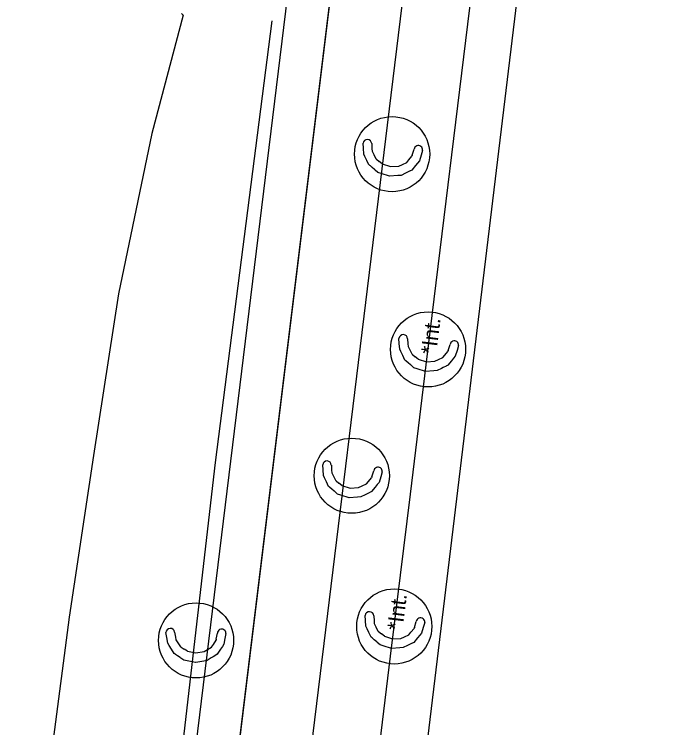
# Model space of a CAD drawing. Extents: x 400935 to 481562, y 415700 to 505362.
# Drawn here: x 481192.5 to 481394.6, y 490514.5 to 490732.9 of the extents above; entities that cross this region are included whole.
import ezdxf

# ---------------------------------------------------------------- set-up
doc = ezdxf.new("R2010")
doc.units = 0
for name, color, linetype in [('Coir Fiber Wattle with PAM Final CELL', 7, 'Continuous'), ('Earth Berm for Slope Drains Final', 7, 'Continuous'), ('Matting on Slope Note Final CELL', 7, 'Continuous'), ('Old_Level_2', 7, 'Continuous'), ('Scratch_Level_3', 7, 'Continuous'), ('Scratch_Level_4', 7, 'Continuous')]:
    doc.layers.add(name, color=color, linetype=linetype)

msp = doc.modelspace()

# ---------------------------------------------------------------- linework, layer by layer
at = {"layer": 'Coir Fiber Wattle with PAM Final CELL'}
for p, q in [((481301.89, 490693.33), (481301.98, 490691.77)), ((481301.98, 490691.77), (481302.03, 490690.98)), ((481302.03, 490690.98), (481302.52, 490690)), ((481314.32, 490689.81), (481314.88, 490691.59)), ((481302.52, 490690), (481303.17, 490688.7)), ((481303.35, 490688.55), (481303.17, 490688.7)), ((481303.35, 490688.55), (481304.21, 490687.85)), ((481313.27, 490688.36), (481314.21, 490689.5)), ((481314.32, 490689.81), (481314.21, 490689.5)), ((481305.14, 490687.11), (481304.21, 490687.85)), ((481305.14, 490687.11), (481307.66, 490686.34)), ((481307.67, 490686.33), (481307.66, 490686.34)), ((481307.67, 490686.33), (481310.21, 490686.45)), ((481310.21, 490686.45), (481311.3, 490686.96)), ((481311.3, 490686.96), (481312.61, 490687.57)), ((481312.61, 490687.57), (481313.27, 490688.36)), ((481289.55, 490594.9), (481289.63, 490593.35)), ((481289.63, 490593.35), (481289.68, 490592.56)), ((481289.68, 490592.56), (481290.17, 490591.57)), ((481301.97, 490591.39), (481302.54, 490593.16)), ((481290.17, 490591.57), (481290.82, 490590.28)), ((481291, 490590.13), (481290.82, 490590.28)), ((481291, 490590.13), (481291.87, 490589.43)), ((481300.92, 490589.94), (481301.87, 490591.07)), ((481301.97, 490591.39), (481301.87, 490591.07)), ((481292.8, 490588.68), (481291.87, 490589.43)), ((481292.8, 490588.68), (481295.31, 490587.91)), ((481295.32, 490587.91), (481297.86, 490588.03)), ((481297.86, 490588.03), (481298.95, 490588.54)), ((481298.95, 490588.54), (481300.27, 490589.15)), ((481300.27, 490589.15), (481300.92, 490589.94)), ((481295.32, 490587.91), (481295.31, 490587.91)), ((481241.59, 490543.81), (481241.84, 490542.28)), ((481241.84, 490542.28), (481241.97, 490541.5)), ((481254.32, 490541.63), (481254.69, 490543.45)), ((481241.97, 490541.5), (481242.57, 490540.57)), ((481242.57, 490540.57), (481243.35, 490539.34)), ((481252.86, 490539.22), (481253.43, 490540.07)), ((481253.43, 490540.07), (481254.25, 490541.3)), ((481254.32, 490541.63), (481254.25, 490541.3)), ((481243.54, 490539.22), (481243.35, 490539.34)), ((481243.54, 490539.22), (481244.48, 490538.61)), ((481245.48, 490537.97), (481244.48, 490538.61)), ((481245.48, 490537.97), (481248.06, 490537.47)), ((481248.07, 490537.47), (481250.59, 490537.85)), ((481250.59, 490537.85), (481251.62, 490538.47)), ((481251.62, 490538.47), (481252.86, 490539.22)), ((481248.07, 490537.47), (481248.06, 490537.47))]:
    msp.add_line(p, q, dxfattribs=at)
for points in [[(481317.46, 490691.27), (481317.01, 490689.78), (481316.48, 490688.04), (481315.95, 490687.4), (481315.31, 490686.62), (481314.16, 490685.23), (481314.13, 490685.21), (481313.73, 490685.02), (481313.66, 490684.99), (481312.81, 490684.56), (481312.21, 490684.27), (481310.89, 490683.62), (481309.85, 490683.55), (481307.31, 490683.39), (481307.3, 490683.39), (481304.79, 490684.19), (481303.81, 490684.51), (481302.95, 490685.24), (481302.76, 490685.39), (481302.03, 490686.02), (481301.48, 490686.49), (481301.35, 490686.61), (481301.07, 490686.84), (481301.06, 490686.85), (481300.41, 490688.21), (481299.82, 490689.42), (481299.47, 490690.15), (481299.34, 490691.9), (481299.24, 490693.44)], [(481305.11, 490592.85), (481304.66, 490591.36), (481304.13, 490589.62), (481303.6, 490588.97), (481302.96, 490588.19), (481301.82, 490586.81), (481301.78, 490586.79), (481301.38, 490586.6), (481301.32, 490586.56), (481300.46, 490586.14), (481299.86, 490585.85), (481298.55, 490585.2), (481297.51, 490585.13), (481294.96, 490584.96), (481294.95, 490584.96), (481292.44, 490585.77), (481291.46, 490586.08), (481290.6, 490586.82), (481290.42, 490586.97), (481289.69, 490587.59), (481289.13, 490588.07), (481289, 490588.18), (481288.72, 490588.42), (481288.72, 490588.43), (481288.06, 490589.79), (481287.47, 490590.99), (481287.12, 490591.72), (481287, 490593.48), (481286.89, 490595.02)], [(481257.29, 490543.41), (481257, 490541.88), (481256.66, 490540.09), (481256.2, 490539.4), (481255.64, 490538.55), (481254.65, 490537.06), (481254.61, 490537.04), (481254.24, 490536.8), (481254.18, 490536.76), (481253.37, 490536.25), (481252.81, 490535.89), (481251.57, 490535.11), (481250.54, 490534.93), (481248.03, 490534.5), (481248.02, 490534.5), (481245.43, 490535.03), (481244.42, 490535.24), (481243.49, 490535.88), (481243.29, 490536.01), (481242.5, 490536.56), (481241.9, 490536.97), (481241.76, 490537.07), (481241.46, 490537.28), (481241.45, 490537.28), (481240.65, 490538.56), (481239.94, 490539.7), (481239.52, 490540.39), (481239.21, 490542.12), (481238.94, 490543.65)]]:
    msp.add_lwpolyline(points, dxfattribs=at)
for centre in [(481308.14, 490690.11), (481295.8, 490591.68), (481248.15, 490541.27)]:
    msp.add_circle(centre, 11.5, dxfattribs=at)
for centre, radius, start, end in [((481300.56, 490693.28), 1.33, 1.9296, 173.0423), ((481316.17, 490691.43), 1.3, 353.0423, 173.0423), ((481288.21, 490594.86), 1.33, 1.9296, 173.0423), ((481303.83, 490593.01), 1.3, 353.0423, 173.0423), ((481240.27, 490543.63), 1.33, 7.986, 179.0986), ((481255.99, 490543.43), 1.3, 359.0986, 179.0986)]:
    msp.add_arc(centre, radius, start, end, dxfattribs=at)
at = {"layer": 'Earth Berm for Slope Drains Final'}
msp.add_lwpolyline([(481271.37, 490730.91), (481254.01, 490595.72), (481232.68, 490411.03), (481219.82, 490308.67), (481217.86, 490293.05)], dxfattribs=at)
at = {"layer": 'Matting on Slope Note Final CELL'}
for p, q in [((481218.64, 490267.48), (481278.21, 490755.15)), ((481244.2, 490732.68), (481234.64, 490696.45)), ((481243.71, 490733.17), (481244.2, 490732.68)), ((481234.64, 490696.45), (481224.44, 490647.33)), ((481224.44, 490647.33), (481216.71, 490597.9)), ((481216.71, 490597.9), (481209.33, 490548.43)), ((481209.33, 490548.43), (481202.79, 490498.86))]:
    msp.add_line(p, q, dxfattribs=at)
at = {"layer": 'Old_Level_2'}
for p, q in [((481312.9, 490633.57), (481312.99, 490632.02)), ((481312.99, 490632.02), (481313.04, 490631.23)), ((481325.33, 490630.06), (481325.89, 490631.83)), ((481313.04, 490631.23), (481313.53, 490630.24)), ((481313.53, 490630.24), (481314.18, 490628.95)), ((481324.28, 490628.61), (481325.22, 490629.74)), ((481325.33, 490630.06), (481325.22, 490629.74)), ((481314.36, 490628.8), (481314.18, 490628.95)), ((481314.36, 490628.8), (481315.22, 490628.1)), ((481316.15, 490627.35), (481315.22, 490628.1)), ((481316.15, 490627.35), (481318.67, 490626.58)), ((481322.31, 490627.21), (481323.62, 490627.82)), ((481323.62, 490627.82), (481324.28, 490628.61)), ((481318.68, 490626.58), (481318.67, 490626.58)), ((481318.68, 490626.58), (481321.22, 490626.7)), ((481321.22, 490626.7), (481322.31, 490627.21)), ((481302.55, 490548.77), (481302.63, 490547.22)), ((481302.63, 490547.22), (481302.68, 490546.43)), ((481302.68, 490546.43), (481303.17, 490545.44)), ((481314.97, 490545.26), (481315.54, 490547.03)), ((481303.17, 490545.44), (481303.82, 490544.14)), ((481313.92, 490543.8), (481314.87, 490544.94)), ((481314.97, 490545.26), (481314.87, 490544.94)), ((481304, 490544), (481303.82, 490544.14)), ((481304, 490544), (481304.87, 490543.3)), ((481305.79, 490542.55), (481304.87, 490543.3)), ((481305.79, 490542.55), (481308.31, 490541.78)), ((481310.86, 490541.9), (481311.95, 490542.4)), ((481311.95, 490542.4), (481313.26, 490543.01)), ((481313.26, 490543.01), (481313.92, 490543.8)), ((481308.32, 490541.78), (481308.31, 490541.78)), ((481308.32, 490541.78), (481310.86, 490541.9))]:
    msp.add_line(p, q, dxfattribs=at)
for points in [[(481328.47, 490631.52), (481328.02, 490630.03), (481327.49, 490628.29), (481326.96, 490627.64), (481326.32, 490626.86), (481325.17, 490625.48), (481325.14, 490625.46), (481324.74, 490625.27), (481324.67, 490625.23), (481323.81, 490624.81), (481323.22, 490624.52), (481321.9, 490623.87), (481320.86, 490623.8), (481318.32, 490623.63), (481318.31, 490623.63), (481315.8, 490624.44), (481314.82, 490624.75), (481313.95, 490625.49), (481313.77, 490625.64), (481313.04, 490626.27), (481312.49, 490626.74), (481312.36, 490626.85), (481312.08, 490627.09), (481312.07, 490627.1), (481311.42, 490628.46), (481310.83, 490629.66), (481310.48, 490630.39), (481310.35, 490632.15), (481310.25, 490633.69)], [(481318.11, 490546.72), (481317.66, 490545.22), (481317.13, 490543.48), (481316.6, 490542.84), (481315.96, 490542.06), (481314.82, 490540.68), (481314.78, 490540.66), (481314.38, 490540.46), (481314.32, 490540.43), (481313.46, 490540.01), (481312.86, 490539.71), (481311.54, 490539.07), (481310.51, 490539), (481307.96, 490538.83), (481307.95, 490538.83), (481305.44, 490539.64), (481304.46, 490539.95), (481303.6, 490540.68), (481303.42, 490540.84), (481302.68, 490541.46), (481302.13, 490541.94), (481302, 490542.05), (481301.72, 490542.29), (481301.72, 490542.29), (481301.06, 490543.65), (481300.47, 490544.86), (481300.12, 490545.59), (481300, 490547.34), (481299.89, 490548.89)]]:
    msp.add_lwpolyline(points, dxfattribs=at)
for centre in [(481319.15, 490630.35), (481308.8, 490545.55)]:
    msp.add_circle(centre, 11.5, dxfattribs=at)
for centre, radius, start in [((481311.57, 490633.53), 1.33, 1.9239), ((481327.18, 490631.68), 1.3, 353.0365), ((481301.21, 490548.73), 1.33, 1.9239), ((481316.82, 490546.87), 1.3, 353.0365)]:
    msp.add_arc(centre, radius, start, 173.0365, dxfattribs=at)
at = {"layer": 'Scratch_Level_3'}
msp.add_lwpolyline([(481267.31, 490239.12), (481273.37, 490288.75), (481283.41, 490337.89), (481289.47, 490387.53), (481295.53, 490437.16), (481301.59, 490486.79), (481307.66, 490536.42), (481313.72, 490586.05), (481319.78, 490635.68), (481344.03, 490834.21), (481350.48, 490883.79), (481356.71, 490933.4), (481362.86, 490983.02), (481368.68, 491032.68), (481374.34, 491082.36), (481382.38, 491131.75), (481382.5, 491182.11), (481388.13, 491231.38), (481392.2, 491280.61), (481394.63, 491329.96)], dxfattribs=at)
at = {"layer": 'Scratch_Level_4'}
for points in [[(481192.51, 489946.27), (481250.03, 489939.44), (481357.88, 490832.14), (481301.55, 490839.02)], [(481243.67, 490365.16), (481301.5, 490838.64), (481323.34, 490835.97), (481265.51, 490362.49)]]:
    msp.add_lwpolyline(points, close=True, dxfattribs=at)

# ---------------------------------------------------------------- texts
at = {"layer": 'Old_Level_2'}
for p in [(481321.62, 490628.6), (481311.31, 490544.12)]:
    msp.add_text('*Int.', height=4.746, rotation=83.0423, dxfattribs=at).set_placement(p)

doc.saveas('drawing.dxf')
